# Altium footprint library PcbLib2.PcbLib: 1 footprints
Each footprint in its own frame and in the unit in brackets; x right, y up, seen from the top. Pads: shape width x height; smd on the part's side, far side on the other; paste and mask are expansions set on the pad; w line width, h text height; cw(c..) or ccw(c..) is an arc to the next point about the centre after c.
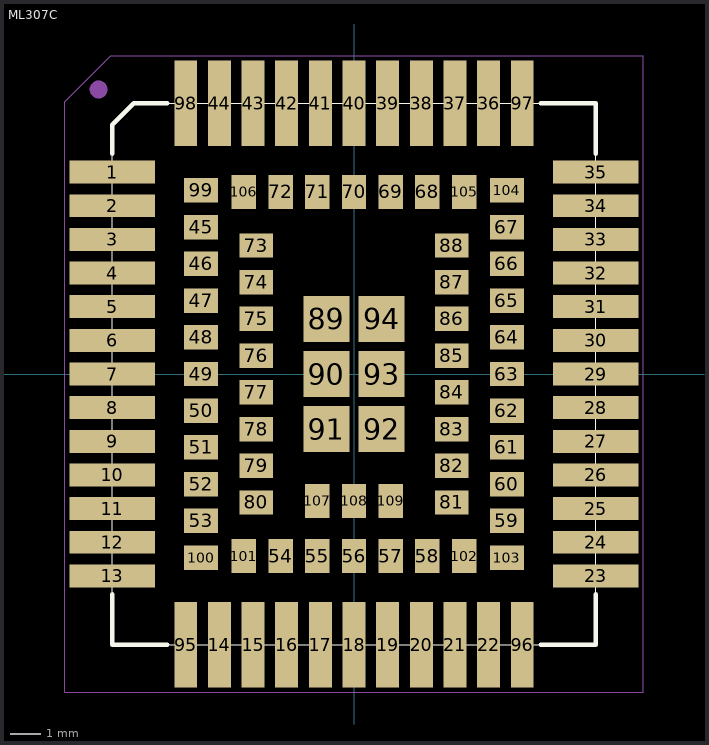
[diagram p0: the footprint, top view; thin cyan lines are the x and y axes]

## ML307C [mm]
height 2.4
pads (109):
  rect 2.8x0.75 smd: 1(-7.9,6.6) 2(-7.9,5.5) 3(-7.9,4.4) 4(-7.9,3.3) 5(-7.9,2.2) 6(-7.9,1.1) 7(-7.9,0) 8(-7.9,-1.1) 9(-7.9,-2.2) 10(-7.9,-3.3) 11(-7.9,-4.4) 12(-7.9,-5.5) 13(-7.9,-6.6) 23(7.9,-6.6) 24(7.9,-5.5) 25(7.9,-4.4) 26(7.9,-3.3) 27(7.9,-2.2) 28(7.9,-1.1) 29(7.9,0) 30(7.9,1.1) 31(7.9,2.2) 32(7.9,3.3) 33(7.9,4.4) 34(7.9,5.5) 35(7.9,6.6)
  rect 0.75x2.8 smd: 14(-4.4,-8.85) 15(-3.3,-8.85) 16(-2.2,-8.85) 17(-1.1,-8.85) 18(0,-8.85) 19(1.1,-8.85) 20(2.2,-8.85) 21(3.3,-8.85) 22(4.4,-8.85) 36(4.4,8.85) 37(3.3,8.85) 38(2.2,8.85) 39(1.1,8.85) 40(0,8.85) 41(-1.1,8.85) 42(-2.2,8.85) 43(-3.3,8.85) 44(-4.4,8.85) 95(-5.5,-8.85) 96(5.5,-8.85) 97(5.5,8.85) 98(-5.5,8.85)
  rect 1.1x0.8 smd: 45(-5,4.8) 46(-5,3.6) 47(-5,2.4) 48(-5,1.2) 49(-5,0) 50(-5,-1.2) 51(-5,-2.4) 52(-5,-3.6) 53(-5,-4.8) 59(5,-4.8) 60(5,-3.6) 61(5,-2.4) 62(5,-1.2) 63(5,0) 64(5,1.2) 65(5,2.4) 66(5,3.6) 67(5,4.8) 73(-3.2,4.2) 74(-3.2,3) 75(-3.2,1.8) 76(-3.2,0.6) 77(-3.2,-0.6) 78(-3.2,-1.8) 79(-3.2,-3) 80(-3.2,-4.2) 81(3.2,-4.2) 82(3.2,-3) 83(3.2,-1.8) 84(3.2,-0.6) 85(3.2,0.6) 86(3.2,1.8) 87(3.2,3) 88(3.2,4.2) 99(-5,6) 100(-5,-6) 103(5,-6) 104(5,6)
  rect 0.8x1.1 smd: 54(-2.4,-5.95) 55(-1.2,-5.95) 56(0,-5.95) 57(1.2,-5.95) 58(2.4,-5.95) 68(2.4,5.95) 69(1.2,5.95) 70(0,5.95) 71(-1.2,5.95) 72(-2.4,5.95) 101(-3.6,-5.95) 102(3.6,-5.95) 105(3.6,5.95) 106(-3.6,5.95) 107(-1.2,-4.15) 108(0,-4.15) 109(1.2,-4.15)
  rect 1.5x1.5 smd: 89(-0.9,1.8) 90(-0.9,0) 91(-0.9,-1.8) 92(0.9,-1.8) 93(0.9,0) 94(0.9,1.8)
Top Overlay:
  lines w0.01: -7.9,-8.85 -7.9,8.15 -7.2,8.85 7.9,8.85 7.9,-8.85 -7.9,-8.85
  lines w0.15: -7.9,-7.2 -7.9,-8.85 -6.1,-8.85 ; -7.9,7.2 -7.9,8.15 -7.2,8.85 -6.1,8.85 ; 6.1,-8.85 7.9,-8.85 7.9,-7.2 ; 6.1,8.85 7.9,8.85 7.9,7.2
Mechanical 1:
  circle w0.3: c-8.35,9.3 r0.141
  lines w0.005: -9.45,-10.4 9.45,-10.4 9.45,10.4 -7.95,10.4 -9.45,8.9 -9.45,-10.4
